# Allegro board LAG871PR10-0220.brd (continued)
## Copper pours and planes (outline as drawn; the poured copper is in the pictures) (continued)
LX_1.05VALWP on TOP (solid shape): 191.56,106.87 191.56,106.11 191.48,106.03 190.44,106.03 190.13,106.33 190.13,106.61 190.37,106.84 191.26,106.84 191.36,106.94 191.49,106.94
LX_1.05VALWP on TOP (solid shape): 190.16,112.86 190.16,111.22 190.35,111.03 191.15,111.03 192.02,110.16 192.02,109.21 191.94,109.14 191.37,109.14 191.13,109.38 190.18,109.38 189.79,109.77 186.57,109.77 186.52,109.82 186.52,112.5 187,112.99 190.04,112.99
LX_1.05VALWP on BOTTOM (solid shape): 191.53,111.18 191.53,110.33 191.21,110.01 191.21,106.33 191.1,106.22 190.23,106.22 190.13,106.32 190.13,107.16 189.81,107.47 188.26,107.47 187.73,108.01 184.47,108.01 184.09,108.39 184.09,111.82 184.28,112.01 190.7,112.01
LX_1.8VALW on BOTTOM (solid shape): 179.33,106.99 179.33,106.23 179.27,106.17 178.31,106.17 178.06,105.91 178.06,105.02 177.87,104.83 175.33,104.83 175.27,104.9 175.27,105.98 175.33,106.04 176.66,106.04 176.92,106.29 176.92,107.12 177.04,107.25 179.08,107.25
LX_1V_PRIM_CORE on TOP (solid shape): 187.59,28.38 187.59,24.89 187.52,24.82 186.7,24.82 186.57,24.95 186.57,25.58 186.38,25.77 186.38,26.92 186.19,27.11 184.79,27.11 184.73,27.17 184.73,27.87 184.79,27.93 185.93,27.93 186.38,28.38 186.38,28.52 186.49,28.63 187.33,28.63
LX_1VS_VCCIO on TOP (solid shape): 83.76,27.74 83.76,27.11 83.7,27.04 82.87,27.04 82.75,26.92 82.75,25.33 82.56,25.14 81.54,25.14 81.35,24.95 81.35,23.93 81.16,23.74 80.52,23.74 80.4,23.87 80.4,27.43 80.78,27.81 83.7,27.81
LX_3V on TOP (solid shape): 189.49,98.93 189.49,98.48 189.6,98.38 189.6,98.27 189.51,98.18 188.71,98.18 188.41,98.48 188.41,98.93 188.54,99.05 189.36,99.05
LX_3V on TOP (solid shape): 196.73,100.64 196.73,95.5 197.94,94.29 197.94,93.97 197.24,93.28 196.98,93.28 195.71,94.55 195.71,96.96 195.23,97.44 194.67,97.44 194.27,97.85 192.79,97.85 192.66,97.72 191.9,97.72 191.85,97.72 191.78,97.8 191.78,98.39 192.34,98.95 192.34,99.68 192.47,99.82 194.85,99.82 194.89,99.85 194.89,100.85 195.12,101.09 196.28,101.09
LX_3V on BOTTOM (solid shape): 198.89,97.4 198.89,95.82 196.92,93.85 196.54,93.85 194,96.39 194,96.64 194.57,97.21 194.57,97.59 194.32,97.85 192.98,97.85 192.28,98.55 188.6,98.55 188.41,98.74 188.41,99.12 188.54,99.24 192.28,99.24 193.36,100.32 195.97,100.32
LX_5V on TOP (solid shape): 46.28,17.18 46.28,16.16 46.1,15.98 43.98,15.98 43.85,16.11 43.85,17.24 43.91,17.3 46.16,17.3
LX_5V on TOP (solid shape): 46.49,27.34 46.49,26.11 46.31,25.93 45.9,25.93 45.63,26.19 45.63,27.08 45.54,27.18 45.54,27.37 45.62,27.45 46.39,27.45
LX_5V on TOP (solid shape): 40.26,28.23 40.26,28 40.29,27.97 40.46,27.79 40.48,27.78 42.32,27.78 42.43,27.9 43.27,27.9 43.37,27.8 43.37,27.2 43.16,26.99 43.16,25.95 43,25.79 42.54,25.79 42.42,25.67 42.42,25.13 42.36,25.06 41.24,25.06 39.76,26.55 39.76,28.29 39.83,28.37 40.13,28.37
LX_5V on BOTTOM (solid shape): 40.22,28.39 40.31,28.35 40.32,28.25 40.43,27.85 40.85,27.89 40.92,27.91 41.22,27.79 41.52,27.91 41.59,27.89 42,27.85 42.12,28.25 42.13,28.35 42.21,28.39 42.48,28.39 44.51,26.36 44.51,23.85 45.15,23.21 45.15,21.87 45.58,21.44 45.58,21.07 45.86,20.78 46.32,20.78 46.93,20.17 46.93,15.92 46.62,15.6 43.12,15.6 42.11,16.62 42.11,16.63 41.62,17.12 41.62,20.84 42.73,21.95 42.73,23.59 42.42,23.89 42.42,23.91 42.41,23.91 39.76,26.55 39.76,28.29 39.87,28.39
LX_5V on IN1: 39.85,28.34 40.16,28.34 40.26,28.25 40.26,27.94 40.43,27.77 42.22,27.77 42.39,27.6 42.39,27.27 42.54,27.12 46.11,27.12 46.26,26.97 46.26,26 44.49,24.24 44.49,16.93 44.26,16.7 41.89,16.7 41.45,17.14 41.45,22.71 40.79,23.37 40.79,25.52 39.76,26.55 39.76,28.25
LX_5V on IN2: 41.72,16.7 41.39,17.03 41.39,22.76 39.78,24.37 39.78,28.27 39.87,28.36 40.15,28.36 40.26,28.26 40.26,27.89 40.38,27.77 41.97,27.77 42.08,27.67 42.08,27.31 42.31,27.07 43.63,27.07 43.71,26.99 43.71,24.01 44.49,23.23 44.49,16.93 44.26,16.7
LX_5V on IN3: 46.1,15.99 42.43,15.99 41.39,17.03 41.39,17.04 41.31,17.12 41.31,22.71 39.78,24.24 39.78,28.24 39.9,28.36 40.15,28.36 40.25,28.26 40.25,27.9 40.38,27.77 40.39,27.76 41.97,27.76 42.07,27.65 42.07,27.41 42.42,27.07 46.12,27.07 46.25,26.93 46.25,26.08 46.14,25.97 45.46,25.97 45.23,25.75 45.23,21 46.27,19.96 46.27,16.16
LX_DDR on TOP (solid shape): 222.89,34.73 222.89,29.08 222.88,29.06 221.38,29.06 221.3,29.14 221.3,30.52 220.67,31.16 220.3,31.16 219.08,32.38 217.47,32.38 217.47,32.8 217.35,32.93 217.35,32.95 216.91,33.13 217.09,32.69 217.12,32.68 217.14,32.64 217.14,32.38 216.86,32.38 216.73,32.25 216.73,29.58 216.63,29.48 215.43,29.48 215.03,29.08 215,29.08 214.75,28.78 215.09,28.58 215.12,28.57 215.2,28.5 215.17,28.4 214.37,27.6 209.95,27.6 209.73,27.82 209.73,30.43 211.72,32.42 211.81,32.42 211.81,32.51 211.95,32.65 211.95,33.3 212.11,33.46 212.11,34.2 212.11,34.2 212.11,34.49 212.36,34.74 212.65,34.74 212.73,34.82 212.77,34.82 212.77,34.86 212.89,34.98 212.89,36.97 213.47,37.55 220.07,37.55
LX_DDR on BOTTOM (solid shape): 215.19,30.34 215.19,26.89 215.08,26.78 210.61,26.78 210.34,27.04 210.34,30.3 210.97,30.93 214.6,30.93
LX_GT on TOP (solid shape): 81.68,71.86 81.68,70.21 81.56,70.1 79.7,70.1 79.57,70.22 79.57,71.11 80.48,72.03 81.52,72.03
LX_GT on BOTTOM (solid shape): 82.15,71.71 82.38,71.71 82.58,71.51 82.58,69.94 81.71,69.94 81.71,69.23 82.58,69.23 82.58,68.93 82.58,67.05 82.26,66.73 76.99,66.73 76.88,66.84 76.88,67.76 78.16,67.76 78.4,68 78.4,71.71 82.15,71.71
LX_SA on TOP (solid shape): 95.64,94.82 95.64,91.81 95.22,91.4 93.26,91.4 93.16,91.5 93.16,93.46 92.84,93.78 92.84,94.49 92.89,94.54 93.98,94.54 94.31,94.87 95.59,94.87
LX_SA on BOTTOM (solid shape): 96.21,96.13 98.83,96.13 98.83,96.13 98.83,95.09 98.82,95.08 96.36,95.08 96.08,94.8 96.08,94.35 95.97,94.25 95.97,93.04 95.27,92.34 93.44,92.34 93.44,93.25 92.63,93.25 92.63,92.34 91.5,92.34 91.32,92.51 91.32,95.27 91.89,95.27 91.89,95.22 91.9,95.17 91.91,95.12 91.94,95.07 91.97,95.03 92.01,94.99 92.05,94.96 92.09,94.94 92.14,94.92 92.19,94.91 92.25,94.91 92.3,94.92 92.35,94.94 92.39,94.96 92.44,94.99 92.47,95.03 92.5,95.07 92.53,95.12 92.54,95.17 92.55,95.22 92.55,95.27 92.54,95.32 92.53,95.37 92.5,95.42 92.47,95.46 92.44,95.5 92.39,95.53 92.35,95.55 92.3,95.57 92.25,95.57 92.19,95.57 92.14,95.57 92.09,95.55 92.05,95.53 92.01,95.5 91.97,95.46 91.94,95.42 91.91,95.37 91.9,95.32 91.89,95.27 91.32,95.27 91.32,95.45 91.86,95.99 93.87,95.99 94.41,96.53 95.81,96.53
RING2 on TOP (solid shape): 299.66,45.76 299.66,45.11 299.65,45.11 299.65,44.38 300.11,43.92 300.11,41.14 299.85,40.89 299.22,40.89 298.84,41.27 298.84,43.38 298.14,44.08 298.14,45.55 298.48,45.89 299.53,45.89
RING2 on TOP (solid shape): 284.91,40.36 285.69,40.36 285.78,40.27 285.78,40.27 285.83,40.22 286.78,40.22 286.78,40.21 287.25,40.21 287.42,40.04 287.42,39.49 287.29,39.36 286.73,39.36 286.73,39.36 286.6,39.36 286.6,39.37 286.31,39.66 285.98,39.66 285.91,39.67 285.84,39.66 285.77,39.66 285.66,39.77 285.66,39.95 285.47,40.15 283.97,40.15 283.92,40.21 283.92,40.3 283.98,40.36 284.91,40.36
RING2 on IN1 (solid shape): 300.3,41.84 300.3,40.89 300.17,40.76 298.96,40.76 298.2,41.52 298.2,41.65 298.58,42.03 300.11,42.03
RING2 on IN1 (solid shape): 287.15,40.06 289.06,40.06 289.06,38.79 287.72,38.79 287.41,39.11 286.84,39.11 286.26,39.68 285.76,39.68 285.69,39.74 285.69,40.06 285.82,40.19 287.03,40.19
RING2_R on TOP (solid shape): 303.22,46.35 303.22,45.65 302.93,45.36 302.17,45.36 301.95,45.14 300.06,45.14 299.93,45.27 299.93,45.8 299.97,45.81 300.16,46.01 300.14,46.28 300.12,46.31 300.2,46.39 300.91,46.39 301.19,46.67 301.19,46.67 301.24,46.72 302.85,46.72
RING2_R on BOTTOM (solid shape): 304.56,46.24 304.56,45.26 305.19,44.63 305.19,44.09 305.04,43.95 304.13,43.95 303.69,44.38 303.69,45.09 303.57,45.21 302.16,45.21 301.97,45.4 301.97,46.11 302.15,46.28 303.3,46.28 303.61,46.59 304.21,46.59
RING2_R on IN4 (solid shape): 306.46,45.14 306.46,44.06 306.33,43.94 304.15,43.94 303.92,44.16 303.92,45.02 304.11,45.21 306.39,45.21
SLEEVE on TOP (solid shape): 304.99,46.45 304.99,45.51 303.41,43.94 302.33,43.94 302.27,44 302.27,44.89 302.49,45.11 303.04,45.11 303.47,45.54 304.46,46.54 304.9,46.54
SLEEVE on TOP (solid shape): 287.43,40.96 287.43,40.47 287.32,40.36 286.83,40.36 286.82,40.37 285.82,40.37 285.66,40.53 283.99,40.53 283.92,40.6 283.92,40.71 283.97,40.76 285.25,40.76 285.64,41.15 287.23,41.15
SLEEVE on IN1 (solid shape): 287.85,41.14 287.85,40.63 287.6,40.38 285.82,40.38 285.63,40.57 285.63,41.14 285.95,41.46 287.53,41.46
SLEEVE on IN1 (solid shape): 303.54,44.57 303.54,44.19 301.95,42.6 301.31,42.6 301.12,42.79 301.12,43.81 302.08,44.76 303.35,44.76
SLEEVE_R on TOP (solid shape): 307.56,46.8 308.12,46.8 308.2,46.72 308.2,46.07 307.59,45.46 307.03,45.46 307.02,45.46 305.48,45.46 305.28,45.66 305.28,46.52 305.37,46.61 305.84,46.61 306.11,46.88 306.11,47.23 306.11,47.23 306.19,47.3 307.05,47.3
SLEEVE_R on BOTTOM (solid shape): 307.71,46.46 307.71,45.59 307.44,45.31 306.48,45.31 306.2,45.04 305.63,45.04 305.42,45.24 305.42,46.37 305.65,46.6 307.57,46.6
SNUB1_CHG on TOP (solid shape): 57.73,73.27 57.73,71.49 57.66,71.43 56.14,71.43 55.44,72.13 55.44,72.7 56.08,73.34 57.66,73.34
SNUB1_IA on TOP (solid shape): 80.65,94.23 80.65,92.7 80.52,92.58 79.64,92.58 79.44,92.77 79.44,93.21 79.25,93.4 78.3,93.4 78.17,93.53 78.17,94.23 78.3,94.35 80.52,94.35
SNUB2_CHG on TOP (solid shape): 58.36,76.13 58.36,73.65 58.24,73.53 57.22,73.53 57.09,73.65 57.09,76.19 57.22,76.32 58.17,76.32
SNUB2_IA on TOP (solid shape): 84.56,81.75 84.56,79.85 84.44,79.73 82.76,79.73 82.68,79.81 82.68,80.83 82.73,80.88 83.54,80.88 83.78,81.11 83.78,81.75 83.9,81.87 84.44,81.87
SNUB_1.05VALWP on TOP (solid shape): 192.63,112.94 192.63,112.38 192.53,112.27 191.73,112.27 191.59,112.13 191.59,111.25 191.51,111.17 190.51,111.17 190.44,111.23 190.44,112.97 190.53,113.06 192.5,113.06
SNUB_1.8VALW on BOTTOM (solid shape): 176.47,107.25 176.47,106.29 176.35,106.17 174.95,106.17 174.76,106.36 174.76,107.25 174.89,107.37 176.35,107.37
SNUB_1V_PRIM_CORE on TOP (solid shape): 188.35,24.19 188.35,23.55 188.28,23.49 186.63,23.49 186.51,23.62 186.51,24.25 186.7,24.44 188.09,24.44
SNUB_1VS_VCCIO on TOP (solid shape): 79.76,24.76 79.76,23.93 79.64,23.81 78.17,23.81 78.05,23.93 78.05,24.44 78.17,24.57 78.75,24.57 79.06,24.89 79.64,24.89
SNUB_3V on TOP (solid shape): 196.09,92.39 196.09,90.74 195.65,90.29 194.38,90.29 194.19,90.48 194.19,92.2 193.87,92.51 193.87,92.7 194.6,93.43 195.05,93.43
SNUB_5V on TOP (solid shape): 45.11,20.86 45.11,20.38 45.6,19.89 45.6,18.88 45.54,18.83 43.97,18.83 43.9,18.89 43.9,19.93 44.34,20.36 44.34,20.85 44.41,20.93 45.05,20.93
SNUB_DDR on TOP (solid shape): 212.76,36.73 212.76,34.99 212.62,34.86 211.65,34.86 211.58,34.92 211.58,35.85 211.29,36.14 210.39,36.14 210.25,36.28 210.25,36.92 210.48,37.15 212.34,37.15
SNUB_GT on TOP (solid shape): 84.62,73.01 84.62,70.41 84.41,70.21 83.19,70.21 83.11,70.29 83.11,71.98 83.4,72.27 83.4,73.19 83.51,73.3 84.33,73.3
SNUB_SA on TOP (solid shape): 95,89.91 95,88.81 94.96,88.77 93.22,88.77 93.09,88.9 92.46,88.9 92.18,89.17 92.18,89.89 92.4,90.1 94.81,90.1
UG1_CHG on TOP (solid shape): 47.87,57.41 47.87,56.65 47.64,56.42 47.64,55.51 47.58,55.46 47.47,55.46 47.42,55.51 47.42,56.47 47.37,56.52 47.37,57.38 47.52,57.53 47.75,57.53
UG1_CHG on BOTTOM (solid shape): 48.97,67.01 49.33,67.01 49.39,66.94 49.39,66.34 49.36,66.31 48.08,66.31 47.79,66.59 47.79,67.65 47.86,67.72 48.26,67.72
UG1_CHG on IN1 (solid shape): 48.41,67.53 48.41,66.76 48.16,66.51 48.16,65.88 48.03,65.75 47.21,65.75 47.08,65.88 47.08,67.4 47.4,67.72 48.22,67.72
UG1_CHG on IN1 (solid shape): 48.01,59.03 48.01,57.08 47.89,56.95 47.89,56.64 47.69,56.45 47.44,56.45 47.25,56.64 47.25,57.46 47.06,57.65 47.06,58.45 46.82,58.69 46.82,58.93 47.15,59.27 47.78,59.27
UG2_CHG on TOP (solid shape): 50.43,54.74 50.43,54.57 49.8,53.93 49.42,53.93 49.4,53.94 48.59,53.94 48.53,54.01 48.53,54.1 48.59,54.16 49.44,54.16 50.15,54.87 50.3,54.87
UG2_CHG on BOTTOM (solid shape): 61.33,82.86 61.68,82.86 61.78,82.76 61.78,82.16 61.72,82.1 60.64,82.1 60.51,82.23 60.51,82.99 60.64,83.12 61.08,83.12
UG2_CHG on IN4 (solid shape): 50.41,54.74 52.01,54.74 52.07,54.69 52.07,53.7 49.85,53.7 49.51,54.04 49.51,54.36 49.99,54.85 50.3,54.85
UG2_CHG on IN4 (solid shape): 61.21,83.01 61.21,82.25 61.07,82.11 61.07,81.1 61.04,81.07 60.06,81.07 59.95,81.19 59.95,82.84 60.32,83.2 61.02,83.2
UG_SA on TOP (solid shape): 97.15,98.15 97.15,96.41 96.42,95.68 93.83,95.68 93.56,95.94 92.91,95.94 92.83,96.02 92.83,96.68 92.89,96.73 94.06,96.73 94.35,96.44 95.66,96.44 96.07,96.85 96.07,98.16 96.19,98.28 97.03,98.28
UG_SA on BOTTOM (solid shape): 97.11,98.19 97.11,97.92 96.84,97.65 96.84,97.28 96.72,97.15 96.09,97.15 95.96,97.28 95.96,98.16 96.09,98.3 97.01,98.3
VOUT_2.5V_MEM on TOP (solid shape): 119.58,28.51 119.58,27.74 120.02,27.3 121.1,27.3 121.35,27.04 121.35,26.47 121.23,26.35 119.39,26.35 119.32,26.41 117.48,26.41 117.04,26.85 117.04,28 117.1,28.06 117.61,28.06 117.61,28.7 117.04,28.7 117.04,28.82 117.16,28.95 119.13,28.95
N14048965 on BOTTOM (solid shape): 22.38,91.18 22.38,90.32 22.68,90.03 22.98,90.03 23.3,89.7 23.3,88.74 23.25,88.69 22.89,88.69 22.85,88.73 22.85,89 22.37,89.48 22.01,89.48 21.64,89.85 21.64,91.18 21.81,91.34 22.22,91.34
N16783222 on TOP (solid shape): 43.37,29.15 43.37,28.57 43.3,28.5 41.42,28.5 41.28,28.64 41.28,29.38 41.48,29.58 42.93,29.58
N17370862 on BOTTOM (solid shape): 50.88,94.13 50.88,93.77 51.22,93.44 51.69,93.44 51.85,93.28 51.85,92.54 51.7,92.39 49.26,92.39 48.96,92.68 48.96,93.4 49.91,94.35 50.66,94.35
N24906879 on TOP (solid shape): 44.46,62.16 44.46,61.27 44.2,61.02 42.93,61.02 42.42,60.51 42.42,58.88 42,58.46 41.23,58.46 41.15,58.54 41.15,59.56 40.77,59.94 40.77,61.11 40.84,61.17 40.84,62.6 40.9,62.67 43.95,62.67
N49223737 on BOTTOM (solid shape): 76.29,87.94 76.29,87.19 75.94,86.84 75.78,86.84 75.55,86.62 75.55,86.06 75.54,86.06 75.54,85.76 75.43,85.64 74.68,85.64 74.56,85.77 74.56,86.8 74.79,87.03 75.61,87.03 75.97,87.4 75.97,87.91 76.08,88.02 76.21,88.02
N49227484 on BOTTOM (solid shape): 76.67,81.11 76.67,80.77 76.89,80.55 77.56,80.55 77.65,80.46 77.65,80.3 77.57,80.22 76.52,80.22 76.39,80.34 75.41,80.34 75.27,80.48 75.27,81.26 75.36,81.34 76.44,81.34
N49231019 on BOTTOM (solid shape): 72.97,71.89 72.97,71.62 73.29,71.3 73.31,71.28 74.09,71.28 74.17,71.2 74.17,71.03 74.1,70.96 72.04,70.96 71.77,71.23 71.77,71.94 71.84,72.01 72.85,72.01

Small or netless copper shapes (teardrops, artwork), in the pictures only: 149 on TOP, 220 on BOTTOM, 1 on IN2

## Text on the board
Ref Des/Silkscreen Bottom: A | DIMM A | DDR4 | REV:A00 | PWB P/N:7YM2P | ALL RIGHT RESERVED | COPYRIGHT 2019 | DIMM B | LTE/WWAN | WLAN/BT
User.Comments: CR_VCOREOUTPUTCAP_1 | LA-G871P | 2020-02-22 | 2019-02-22 | EDC40 | Voilin
BODY_CENTER: L7 | L8 | L9 | L10 | GND3 | VCC | IN4
User.12: 307.83 | 140.95 | 82.50 | 9.28 | 2.22 | 77.70 | 0.00 | 73.50 | 34.49 | 60.50
User.13: 317.50 | 114.30
User.16: 83.12 | 31.30 | 7.90 | 70.05 | 272.35 | 254.65 | 83.10 | 224.36 | 205.75 | 121.78 | 46.25 | 6.59 | 5.88 | 0.00 | 0.82 | 301.08 | 277.05 | 187.45 | 110.25 | 75.28 | 58.10 | 50.35 | 38.75 | 22.34 | 20.05 | 8.17 | 3.60 | 20.45 | 14.94 | 54.20 | 71.85 | 37.46 | 26.18 | 6.18 | 33.15 | 79.00 | 69.40 | 22.00 | 6.15 | 14.00
User.20: 317.50 | 114.30
User.24: LAYER | NO. | L6 | L7 | L8 | L9 | L10 | L3 | L4 | L5 | L1 | L2 | LA-G871P | GND3 | VCC | GND1 | BOT | GND2 | IN4 | TOP | IN1 | IN2 | IN3 | DUMMY COPPER | LS-G871P | Secret Level | Issued | Decipherment date | BOARD Thickness(mm) | PROJECT | DRAW BY | BOARD NO. | Date | COMPAL ELECTRONICS. INC. | Secret data | REV: | 195.5 | 193.5 | -3 | -5 | 87 | 107 | 183 | 0.45 | 180.5 | 182 | 94.15 | 101.5 | Print white paint on TOP silkscreen | 187 | 188.5 | 20 | 30 | REV:0.3 | (TOP) | 42.5 | X:91.27 | Y:64.53 | X:91.38 | Y:26.77 | 15 | 0 | X:117.91 | Y:13.2 | X:230.18 | Y:177.3 | 175.5 | 148 | X:256.71 | Y:163.73 | X:256.82 | Y:125.97 | Print white paint on BOT silkscreen | 160.5 | 170.5 | 3.5 | 2 | 3mm | 89 | 96.35 | 10 | 8.5 | 190.05 | no copper for every layer | 7.5 | 83.5 | 103.5 | ZORA-ZHU | 2018-12-25 | 2019-12-25 | 1.0 | EDC40 | 10% | 0.3 | -4 | 1 | 5.5 | 18 | 24 | 30.07 | 33.07 | 37.09 | 38.59 | 43.59 | 47.09 | 45.09 | 51 | 73.09 | 70.09 | 94.7 | 102.09 | 100.09 | 108.09 | 134 | 139 | 149.09 | 174.04 | 199 | 209.09 | 214.09 | 240 | 246 | 248 | 253.39 | 275 | 278 | 297.09 | 303 | 301 | 304.5 | 309.5 | 311 | 315.02 | 318.02 | 324.09 | 330.09 | 342.59 | 347.09 | 352.09 | R5X4 | R2X4 | Tooling Hole:2mm x3 | Tooling Hole:2.7mm(+/-1.5mil) x4 | Barcode area:8X8 on top side only | Notes: | 1.To Use 2mm(min) router | for breakaway | 2.Refer to detail 2M,4M,8M, | 10M for TAB spec. | REV:0.3(TOP) | F | 0.127mm | 356.09 | 200.5
User.43: L2/4 | L4/7 | L7/9 | L2 | L9 | Ref
User.45: STACK-UP SETTING OK | FIGURE | SIZE | 8.0 | 20.0 | 22.0 | 28.0 | 91.0 | 102.0 | 122.0 | 126.0 | 146.0 | 157.0 | 30.0 | 31.0 | 35.0 | 43.0 | 45.0 | 63.0 | 65.0 | 71.0 | 47.0x20.0 | 49.0x28.0 | 55.0x24.0 | 55.0x28.0 | 63.0x31.0 | 67.0x28.0 | 75.0x24.0 | 79.0x28.0 | 94.0x43.0 | 98.0x28.0 | 110.0x24.0 | 142.0x102.0 | 33.0x28.0 | DRILL CHART: TOP to BOTTOM | ALL UNITS ARE IN MILS | TOLERANCE | +3.0/-3.0 | +2.0/-2.0 | PLATED | NON-PLATED | QTY | 7398 | 33 | 19 | 18 | 1 | 6 | 2 | 4 | 7
